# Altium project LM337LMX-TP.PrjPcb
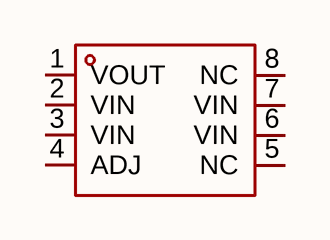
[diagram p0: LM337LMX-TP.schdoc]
1 sheet, 1 parts. Net scope: global (net labels, ports and power ports of the same name join across sheets).

## Sheet LM337LMX-TP.schdoc
size 127 x 101 mm

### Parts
U?  lm337lmx-tp  [SOP-8_L4.9-W3.9-P1.27-LS6.0-BL]  (value not drawn)

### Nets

Not connected (* = marked no-connect by the designer): U? 1(VOUT) 2(VIN) 3(VIN) 4(ADJ) 5(NC) 6(VIN) 7(VIN) 8(NC)

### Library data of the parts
U? = lm337lmx-tp: 输出极性:负极;工作电压:-;输出电压:1.2V~37V;输出电流:1.5A;电源纹波抑制比(PSRR):77dB@(120Hz);输出类型:可调;; Manufacturer: TECH PUBLIC(台舟); AddInBom: yes; ModelId: 75c24a7891ee4dd6bdac16a7163ff87e; ModelName: SOP-8_L4.9-W3.9-P1.27-LS6.0-BL-1; ModelTransform: 192.913,236.22,0,0,0,0,-0.393,2.749,0; Output Configuration: 负极; Output Current: 1.5A; Noise: 0.003%Vout; Output Type: 可调; Number of Outputs: 1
